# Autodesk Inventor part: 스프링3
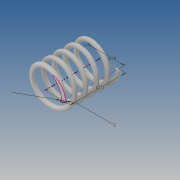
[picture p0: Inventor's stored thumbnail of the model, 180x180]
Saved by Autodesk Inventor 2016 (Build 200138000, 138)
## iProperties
Created: 2016-10
Part Number: 스프링3
Material: Generic
Document SubType Name: Modeling
Designer: Administrator
Density: 1 g/cm^3
Appearance: Default
Mass: 0.874294 g
Surface Area: 17.7466 cm^2
Volume: 0.874294 cm^3
Author: Administrator
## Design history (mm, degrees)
sketch "스케치1"
  geometry: L1 (0, 0)-(-9, 0); L2 (-9, 0)-(-9, -27); L3 (-9, -27)-(0, -27); L4 (0, -27)-(0, 0); C1 r 1 at (-9, 0)
  constraints: 8 end point, 2 parallel, 1 centre point, 1 coincident, 1 horizontal, 1 perpendicular
  dimensions: "d0" = 2 diameter of C1; "d1" = 27 distance of L1.end L2.end (derived); "d2" = 18 diameter of L2 L4
feature "코일1" pitch "d3" = 10; turns "d5" = 5; dims "d4" = 27 (= d1), "d6" = 0, angle "d7" = 90 deg, angle "d8" = 90 deg, "d9" = 0, "d10" = 0
sketch "스케치2"
  geometry: L1 (10, 0)-(8, 0) reference; 1 further point
  constraints: 1 horizontal alignment
  node "절단 모서리 투영1"
extrude "돌출1" cut sketch "스케치2" stored distance "d11" = 10; taper "d12" = 0 deg
node "작업 평면3"
sketch "스케치3"
  geometry: L1 (-1, 0)-(1, 0) reference; 1 further point
  constraints: 1 horizontal alignment
extrude "돌출2" cut sketch "스케치3" stored distance "d14" = 0; taper "d15" = 0 deg
node "솔리드1"
node "절단 모서리 투영2"
other parameters: "d13" = 90 deg
